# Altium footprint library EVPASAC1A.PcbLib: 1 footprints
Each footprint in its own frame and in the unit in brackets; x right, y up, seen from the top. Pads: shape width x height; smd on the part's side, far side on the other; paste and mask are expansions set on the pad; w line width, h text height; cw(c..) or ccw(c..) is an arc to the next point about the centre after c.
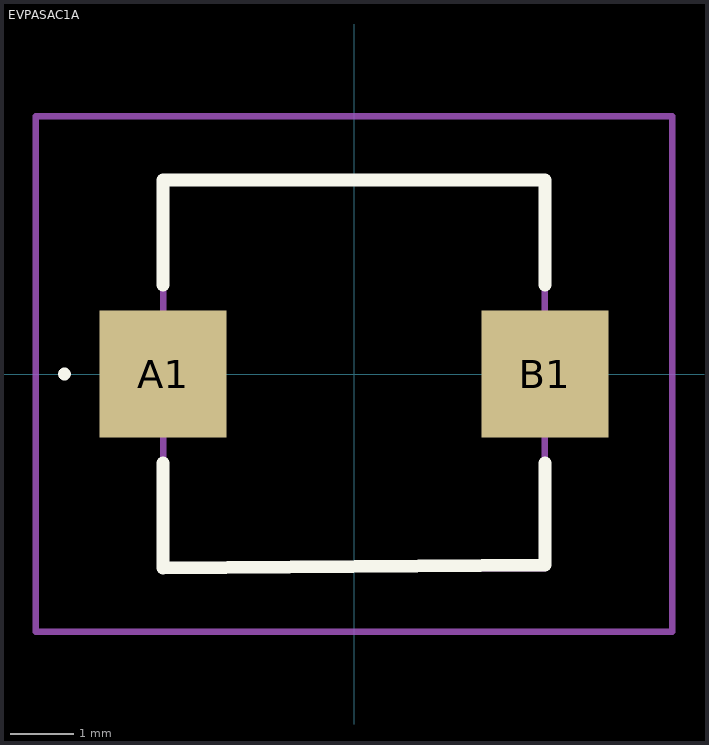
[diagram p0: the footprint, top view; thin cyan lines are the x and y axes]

## EVPASAC1A [mm]
pads (2):
  rect 2x2 smd: A1(-3,0) B1(3,0)
Top Overlay:
  lines w0.1: -4.6,0 -4.6,0 ; -4.6,0 ccw(c-4.55,0) -4.5,0 ; -4.6,0 cw(c-4.55,0) -4.5,0 ; -4.5,0 -4.5,0
  lines w0.2: -3,-1.4 -3,-3.05 3,-3 3,-1.4 ; -3,1.4 -3,3.05 3,3.05 3,1.4
Mechanical 15:
  lines w0.1: -3,-3.05 3,-3.05 3,3.05 -3,3.05 -3,-3.05
Mechanical 20:
  lines w0.1: -5,-4.05 5,-4.05 5,4.05 -5,4.05 -5,-4.05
